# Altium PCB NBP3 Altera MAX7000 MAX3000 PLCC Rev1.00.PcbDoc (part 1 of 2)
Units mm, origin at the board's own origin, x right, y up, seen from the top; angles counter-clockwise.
Board outline 69 x 80.99 mm, 2 copper layers (Top Layer, Bottom Layer); 33 components, 75 nets, 412 pads, 171 vias.
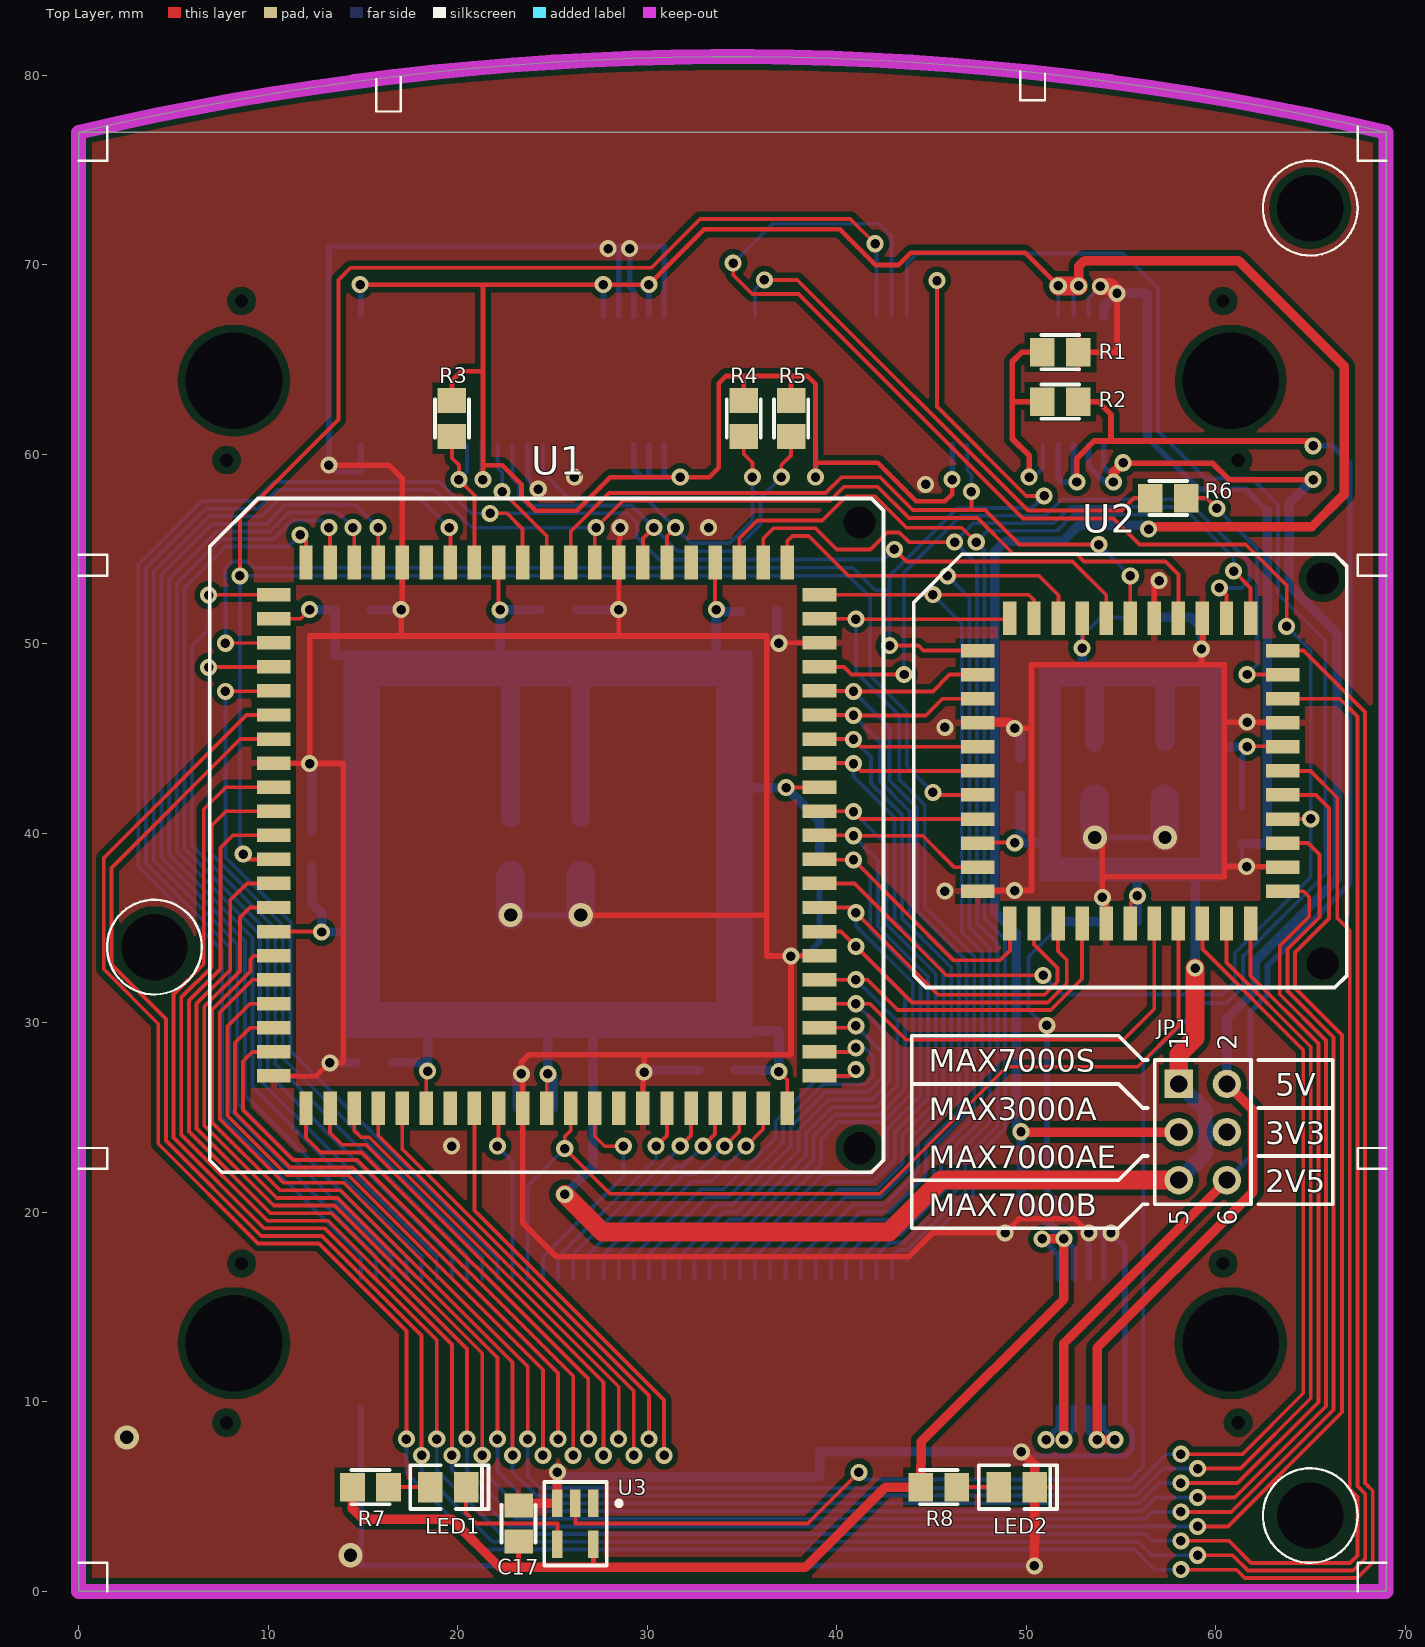
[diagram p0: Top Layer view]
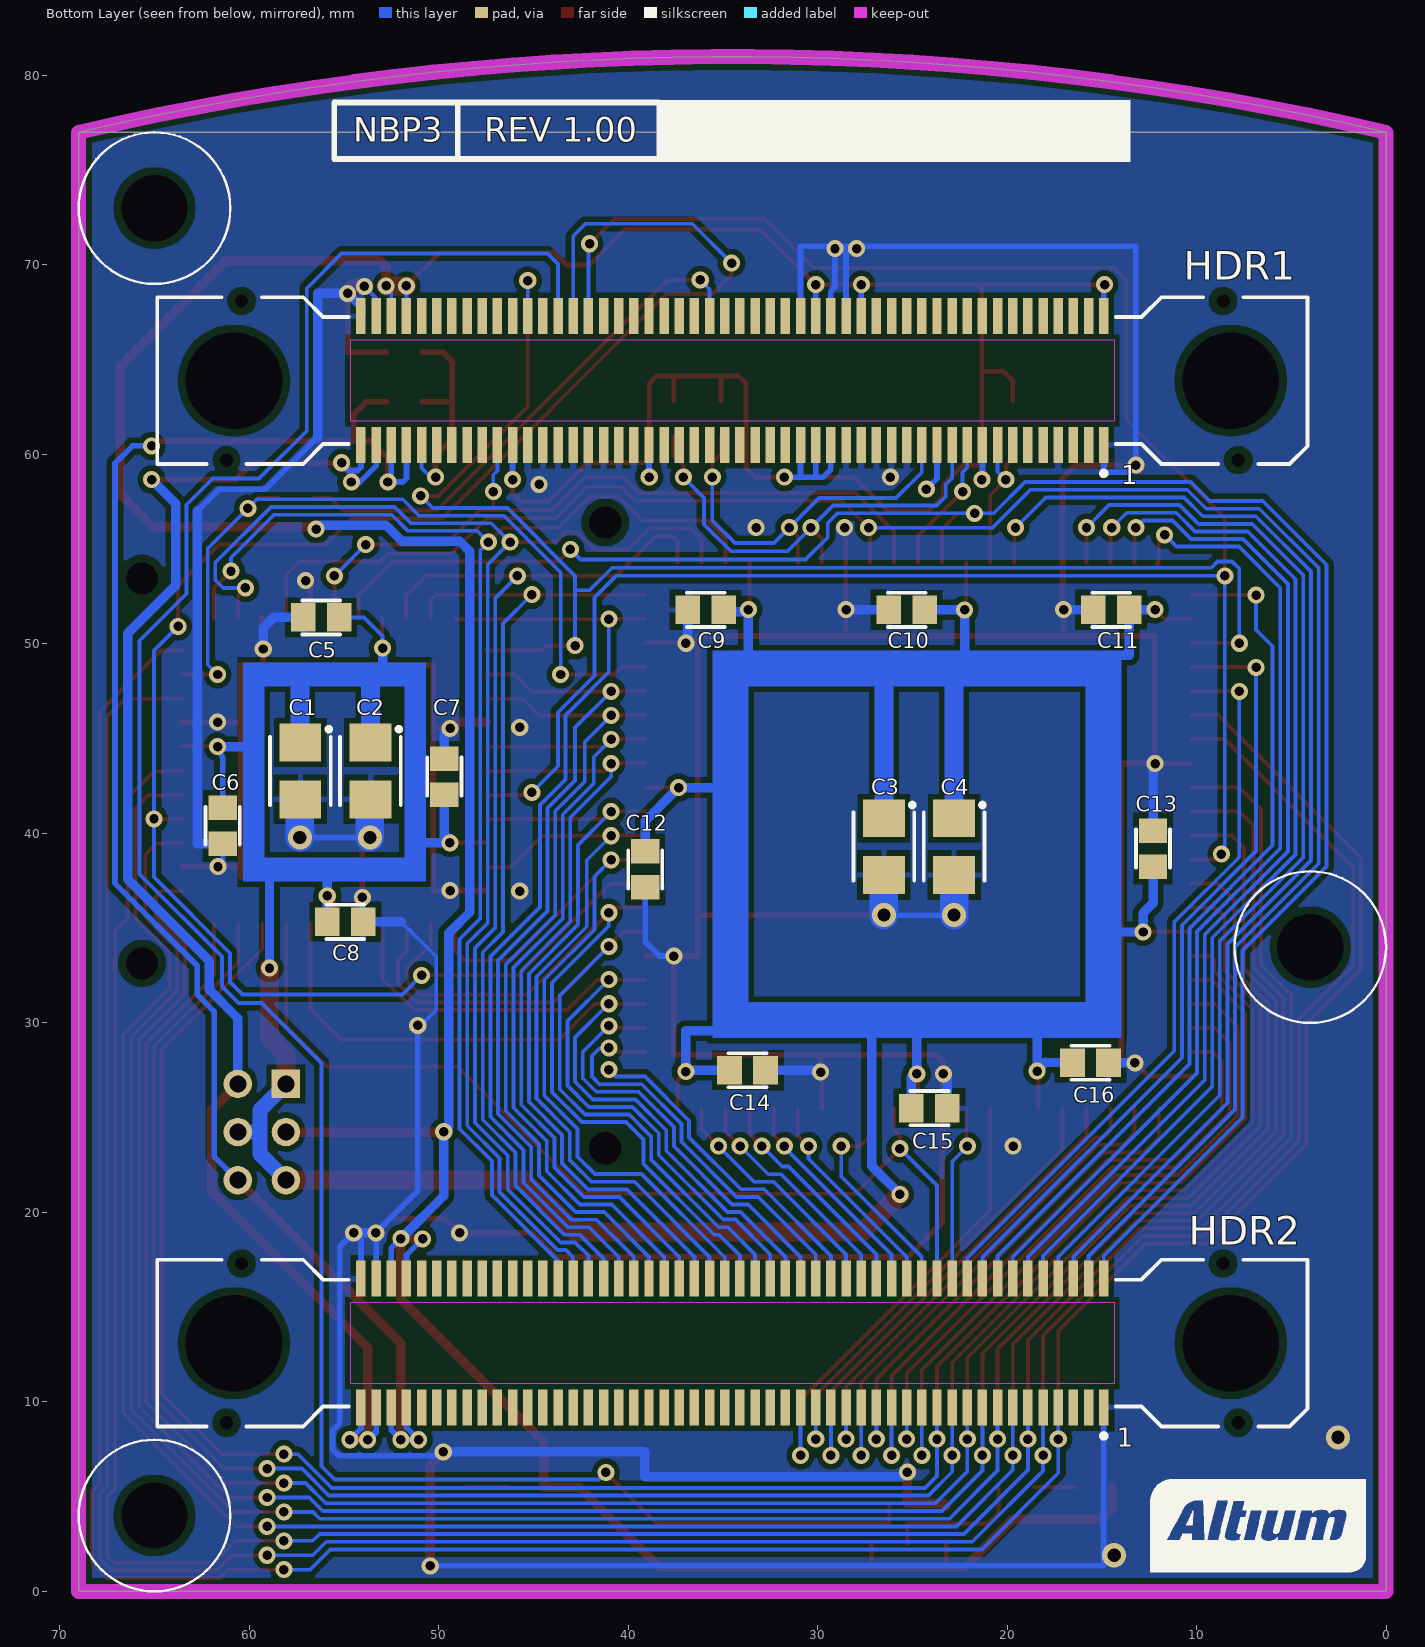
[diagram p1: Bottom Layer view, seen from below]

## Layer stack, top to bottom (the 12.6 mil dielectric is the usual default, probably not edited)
Top Layer: signal copper 0.0356
Dielectric: core 0.32, FR-4, Dk 4.8
Bottom Layer: signal copper 0.0356

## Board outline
0,0 0,77 ccw(c0.001,77) 0.001,77 cw(c34.5,-69.801) 0.001,77 69,77 69,0

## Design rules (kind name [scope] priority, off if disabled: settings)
Clearance Clearance_Unplated_Pads [PadIsPlated = 'False'] p1: gap=0.4 // Slightly larger clearance around unplated holes
Clearance Clearance_Polygons [InPolygon] p2: gap=0.3
Clearance [All] p3: gap=0.2
ComponentClearance [All] p1: gap=0.2 collisioncheckmode=3 verticalgap=0.254 showdistances=FALSE
FabricationTestPointUsage TestPointUsage [All] p1 off: valid=0 allowmultiple=FALSE
FabricationTestpoint Testpoint [All] p1 off: side=3 testpointundercomponent=TRUE minsize=1.016 maxsize=2.54 preferedsize=1.524 minholesize=0 maxholesize=1.016 preferedholesize=0.813 testpointgrid=0.025 allowsidetop=TRUE allowsidebottom=TRUE usegrid=TRUE gridtolerance=0
HoleSize [All] p1: absolutevalues=TRUE maxlimit=5.2 minlimit=0.4 maxpercent=80.000 minpercent=20.000
PlaneClearance [All] p1: clearance=0.5
PlaneConnect [All] p1: planeconnectstyle=Relief reliefexpansion=0.5 reliefentries=4 reliefconductorwidth=0.25 reliefairgap=0.25
PolygonConnect PolygonConnect_Satellite_ID_Pads [InPadClass('Satellite ID Pads')] p1: connectstyle=NoConnect reliefconductorwidth=0.254 reliefentries=4 polygonreliefangle="90 Angle"
PolygonConnect [All] p2: connectstyle=Relief reliefconductorwidth=0.3 reliefentries=4 polygonreliefangle="90 Angle"
RoutingVias [All] p1: holewidth=0.5 width=0.9 viastyle="Through Hole" minholewidth=0.5 minwidth=0.9 maxholewidth=0.7 maxwidth=1.27
SMDNeckDown [All] p1: percent=100.000
SilkscreenOverComponentPads [All] p1: minsilkscreentomaskgap=0.254
SolderMaskExpansion SolderMaskExpansion_Vias [Isvia] p1: expansion=-0.65
SolderMaskExpansion [All] p2: expansion=0.1
Width Width_Power_Nets [InNetClass('Power Nets')] p1: maxlimit=2.5 minlimit=0.15 preferedwidth=0.25
Width [All] p2: maxlimit=1.5 minlimit=0.2 preferedwidth=0.2
21 further rules are at their usual default settings.

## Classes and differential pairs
pad class "Satellite ID Pads": HDR1-36 HDR1-38 HDR2-42
net class "Power Nets": 5V GND VCC VCC_FPGA VCCINT

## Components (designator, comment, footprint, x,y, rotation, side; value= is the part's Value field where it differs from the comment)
C1 "10uF" MCCT-B 57.3,43.3 r270 bottom
C2 "10uF" MCCT-B 53.6,43.3 r270 bottom
C3 "10uF" MCCT-B 26.5,39.3 r270 bottom
C4 "10uF" MCCT-B 22.8,39.3 r270 bottom
C5 "0.1uF" CC2012-0805#1 56.2,51.4 r0 bottom
C6 "0.1uF" CC2012-0805#1 61.4,40.4 r270 bottom
C7 "0.1uF" CC2012-0805#1 49.7,43 r90 bottom
C8 "0.1uF" CC2012-0805#1 54.928,35.334 r180 bottom
C9 "0.1uF" CC2012-0805#1 35.9,51.8 r180 bottom
C10 "0.1uF" CC2012-0805#1 25.3,51.8 r180 bottom
C11 "0.1uF" CC2012-0805#1 14.5,51.8 r180 bottom
C12 "0.1uF" CC2012-0805#1 39.1,38.1 r270 bottom
C13 "0.1uF" CC2012-0805#1 12.3,39.2 r270 bottom
C14 "0.1uF" CC2012-0805#1 33.7,27.5 r180 bottom
C15 "0.1uF" CC2012-0805#1 24.1,25.5 r180 bottom
C16 "0.1uF" CC2012-0805#1 15.6,27.9 r180 bottom
C17 "0.1uF" CC2012-0805#2 23.217,3.571 r90 top
HDR1 "54075-1009" 54075 34.5,63.9 r0 bottom locked
HDR2 "54075-1009" 54075 34.5,13.1 r0 bottom locked
JP1 "Header 3X2" HDR2X3 58.06,26.78 r270 top
LED1 "HSMG-C170" "SMD _LED" 19.5,5.5 r180 top locked
LED2 "HSMH-C170" "SMD _LED" 49.5,5.5 r180 top locked
R1 "680R" CC2012-0805#1 51.8,65.4 r0 top
R2 "82R" CC2012-0805#1 51.8,62.787 r180 top
R3 "4K7" CC2012-0805#1 19.7,61.9 r270 top
R4 "4K7" CC2012-0805#1 35.1,61.9 r270 top
R5 "4K7" CC2012-0805#1 37.6,61.9 r270 top
R6 "100R" CC2012-0805#1 57.5,57.7 r0 top
R7 "270R" CC2012-0805#1 15.4,5.5 r0 top
R8 "270R" CC2012-0805#1 45.4,5.5 r0 top
U1 "PLCC84 SM Socket" PLCC84_SKT_SM 24.7,39.9 r0 top
U2 "PLCC44 SM Socket" PLCC44_SKT_SM 55.5,43.3 r0 top
U3 "SN74LVC1G04DBV" SO-G5/P.95 26.217,3.571 r180 top

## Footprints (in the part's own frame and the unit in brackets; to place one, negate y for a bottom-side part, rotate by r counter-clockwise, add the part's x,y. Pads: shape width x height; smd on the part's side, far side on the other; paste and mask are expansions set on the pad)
54075 [mm] "Connector; Docking Station, Receptacle; 100 Position; Vertical"
  rect 0.5x1.9 smd: 1(-19.6,3.4) 2(-19.6,-3.4) 3(-18.8,3.4) 4(-18.8,-3.4) 5(-18,3.4) 6(-18,-3.4) 7(-17.2,3.4) 8(-17.2,-3.4) 9(-16.4,3.4) 10(-16.4,-3.4) 11(-15.6,3.4) 12(-15.6,-3.4) 13(-14.8,3.4) 14(-14.8,-3.4) 15(-14,3.4) 16(-14,-3.4) 17(-13.2,3.4) 18(-13.2,-3.4) 19(-12.4,3.4) 20(-12.4,-3.4) 21(-11.6,3.4) 22(-11.6,-3.4) 23(-10.8,3.4) 24(-10.8,-3.4) 25(-10,3.4) 26(-10,-3.4) 27(-9.2,3.4) 28(-9.2,-3.4) 29(-8.4,3.4) 30(-8.4,-3.4) 31(-7.6,3.4) 32(-7.6,-3.4) 33(-6.8,3.4) 34(-6.8,-3.4) 35(-6,3.4) 36(-6,-3.4) 37(-5.2,3.4) 38(-5.2,-3.4) 39(-4.4,3.4) 40(-4.4,-3.4) 41(-3.6,3.4) 42(-3.6,-3.4) 43(-2.8,3.4) 44(-2.8,-3.4) 45(-2,3.4) 46(-2,-3.4) 47(-1.2,3.4) 48(-1.2,-3.4) 49(-0.4,3.4) 50(-0.4,-3.4) 51(0.4,3.4) 52(0.4,-3.4) 53(1.2,3.4) 54(1.2,-3.4) 55(2,3.4) 56(2,-3.4) 57(2.8,3.4) 58(2.8,-3.4) 59(3.6,3.4) 60(3.6,-3.4) 61(4.4,3.4) 62(4.4,-3.4) 63(5.2,3.4) 64(5.2,-3.4) 65(6,3.4) 66(6,-3.4) 67(6.8,3.4) 68(6.8,-3.4) 69(7.6,3.4) 70(7.6,-3.4) 71(8.4,3.4) 72(8.4,-3.4) 73(9.2,3.4) 74(9.2,-3.4) 75(10,3.4) 76(10,-3.4) 77(10.8,3.4) 78(10.8,-3.4) 79(11.6,3.4) 80(11.6,-3.4) 81(12.4,3.4) 82(12.4,-3.4) 83(13.2,3.4) 84(13.2,-3.4) 85(14,3.4) 86(14,-3.4) 87(14.8,3.4) 88(14.8,-3.4) 89(15.6,3.4) 90(15.6,-3.4) 91(16.4,3.4) 92(16.4,-3.4) 93(17.2,3.4) 94(17.2,-3.4) 95(18,3.4) 96(18,-3.4) 97(18.8,3.4) 98(18.8,-3.4) 99(19.6,3.4) 100(19.6,-3.4)
  round 0.5 hole 0.7 unplated: MH1(-26.7,4.2) MH2(-25.9,-4.2) MH3(26.7,4.2) MH4(25.9,-4.2)
  round 4.8 hole 5.1 unplated: MH5(-26.3,0) MH6(26.3,0)
  Top Layer keep-out region: -20.15,2.15 20.15,2.15 20.15,-2.15 -20.15,-2.15
  silkscreen extent -30.35,-4.4 30.35,5.02
CC2012-0805#1 [mm]
  rect 1.3x1.5 smd: 1(-0.95,0) 2(0.95,0)
  silkscreen extent -1,-0.9 1,0.9
CC2012-0805#2 [mm]
  rect 1.271x1.5 smd: 1(-0.95,0) 2(0.95,0)
  silkscreen extent -1,-0.9 1,0.9
HDR2X3 [mm] "Connector; Header; 3x2 Position"
  rect 1.5x1.5 hole 0.9: 1(0,0)
  round 1.5 hole 0.9: 2(0,2.54) 3(2.54,0) 4(2.54,2.54) 5(5.08,0) 6(5.08,2.54)
  silkscreen extent -1.27,-1.27 6.35,3.81
MCCT-B [mm]
  rect 2x2.2 smd: 1(-1.5,0) 2(1.5,0)
  silkscreen extent -2.3,-1.6 1.8,1.6
PLCC44_SKT_SM [mm] "Socket, PLCC44, surface mount"
  rect 0.71x1.78 smd: 1(0,8.05) 2(-1.27,8.05) 3(-2.54,8.05) 4(-3.81,8.05) 5(-5.08,8.05) 6(-6.35,8.05) 18(-6.35,-8.05) 19(-5.08,-8.05) 20(-3.81,-8.05) 21(-2.54,-8.05) 22(-1.27,-8.05) 23(0,-8.05) 24(1.27,-8.05) 25(2.54,-8.05) 26(3.81,-8.05) 27(5.08,-8.05) 28(6.35,-8.05) 40(6.35,8.05) 41(5.08,8.05) 42(3.81,8.05) 43(2.54,8.05) 44(1.27,8.05)
  rect 1.78x0.71 smd: 7(-8.05,6.35) 8(-8.05,5.08) 9(-8.05,3.81) 10(-8.05,2.54) 11(-8.05,1.27) 12(-8.05,0) 13(-8.05,-1.27) 14(-8.05,-2.54) 15(-8.05,-3.81) 16(-8.05,-5.08) 17(-8.05,-6.35) 29(8.05,-6.35) 30(8.05,-5.08) 31(8.05,-3.81) 32(8.05,-2.54) 33(8.05,-1.27) 34(8.05,0) 35(8.05,1.27) 36(8.05,2.54) 37(8.05,3.81) 38(8.05,5.08) 39(8.05,6.35)
  round 1.4 hole 1.7 unplated: M1(10.16,10.16) M2(10.16,-10.16)
  silkscreen extent -11.43,-11.43 11.43,11.43
PLCC84_SKT_SM [mm] "Socket, PLCC84, surface mount"
  rect 0.71x1.78 smd: 1(0,14.4) 2(-1.27,14.4) 3(-2.54,14.4) 4(-3.81,14.4) 5(-5.08,14.4) 6(-6.35,14.4) 7(-7.62,14.4) 8(-8.89,14.4) 9(-10.16,14.4) 10(-11.43,14.4) 11(-12.7,14.4) 33(-12.7,-14.4) 34(-11.43,-14.4) 35(-10.16,-14.4) 36(-8.89,-14.4) 37(-7.62,-14.4) 38(-6.35,-14.4) 39(-5.08,-14.4) 40(-3.81,-14.4) 41(-2.54,-14.4) 42(-1.27,-14.4) 43(0,-14.4) 44(1.27,-14.4) 45(2.54,-14.4) 46(3.81,-14.4) 47(5.08,-14.4) 48(6.35,-14.4) 49(7.62,-14.4) 50(8.89,-14.4) 51(10.16,-14.4) 52(11.43,-14.4) 53(12.7,-14.4) 75(12.7,14.4) 76(11.43,14.4) 77(10.16,14.4) 78(8.89,14.4) 79(7.62,14.4) 80(6.35,14.4) 81(5.08,14.4) 82(3.81,14.4) 83(2.54,14.4) 84(1.27,14.4)
  rect 1.78x0.71 smd: 12(-14.4,12.7) 13(-14.4,11.43) 14(-14.4,10.16) 15(-14.4,8.89) 16(-14.4,7.62) 17(-14.4,6.35) 18(-14.4,5.08) 19(-14.4,3.81) 20(-14.4,2.54) 21(-14.4,1.27) 22(-14.4,0) 23(-14.4,-1.27) 24(-14.4,-2.54) 25(-14.4,-3.81) 26(-14.4,-5.08) 27(-14.4,-6.35) 28(-14.4,-7.62) 29(-14.4,-8.89) 30(-14.4,-10.16) 31(-14.4,-11.43) 32(-14.4,-12.7) 54(14.4,-12.7) 55(14.4,-11.43) 56(14.4,-10.16) 57(14.4,-8.89) 58(14.4,-7.62) 59(14.4,-6.35) 60(14.4,-5.08) 61(14.4,-3.81) 62(14.4,-2.54) 63(14.4,-1.27) 64(14.4,0) 65(14.4,1.27) 66(14.4,2.54) 67(14.4,3.81) 68(14.4,5.08) 69(14.4,6.35) 70(14.4,7.62) 71(14.4,8.89) 72(14.4,10.16) 73(14.4,11.43) 74(14.4,12.7)
  round 1.4 hole 1.7 unplated: M1(16.51,16.51) M2(16.51,-16.51)
  silkscreen extent -17.78,-17.78 17.78,17.78
"SMD _LED" [mm]
  rect 1.3x1.6 smd: 1(0.95,0) 2(-0.95,0)
  silkscreen extent -2.13,-1.15 2,1.15
SO-G5/P.95 [mm]
  rect 0.55x1.45 smd: 1(-0.95,-1.075) 2(0,-1.075) 3(0.95,-1.075) 4(0.95,1.075) 5(-0.95,1.075)
  silkscreen extent -2.43,-2.2 1.65,2.2

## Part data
C1 C2 C3 C4: library part CAP_POLAR, "Polar Capacitor"
C5 C6 C7 C8 C9 C10 C11 C12 C13 C14 C15 C16 C17: library part CAP, "Capacitor"
HDR1 HDR2: "Board-to-Board, Docking Station, 0.80mm (.031\") Pitch, Shielded Receptacle, Vertical, Ultra Low Profile, SMT"
JP1: "Header, 3-Pin, Dual row"
LED1 LED2: library part HSMX-C670, "Typical RED GaAs SMD LED Agilent make"
R1 R2 R3 R4 R5 R6 R7 R8: library part RES, "Resistor"
U1: library part EPM7160SLC84-10, "MAX 7000S 5V In-System Programmable CPLD, 160 Macrocells, 84-Pin PLCC, Speed Grade 10, Commercial Grade"
U2: library part EPM3032ALC44-10, "MAX 3032, 44-Pin PLCC, Speed Grade 10, Commercial Grade"
U3: library part SN74AHC1G04DBVR

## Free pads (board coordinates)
  round 3.2 hole 3.5 unplated: LP(4,34) LP(65,4) LP(65,73)

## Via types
v1: diameter 0.9, hole 0.5, Top Layer to Bottom Layer, 165 vias
v2: diameter 1.27, hole 0.7, Top Layer to Bottom Layer, 6 vias

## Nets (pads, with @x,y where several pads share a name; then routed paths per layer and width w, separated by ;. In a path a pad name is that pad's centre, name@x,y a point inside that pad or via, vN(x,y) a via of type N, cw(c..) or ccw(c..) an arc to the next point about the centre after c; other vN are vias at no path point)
5V: HDR1.97 HDR1.99 HDR2.97 HDR2.99 JP1.2 | length 84.1
  Top Layer w0.3: v1(55.118,59.563) 55.601,59.538 59.842,59.538 60.706,58.674 v1(65.151,58.674)
  Top Layer w0.5: v1(54.61,58.547) 54.61,59.055 v1(55.118,59.563) ; v1(54.686,8.001) v1(53.746,8.001) 53.746,12.852 61.976,21.082 61.976,25.404 JP1.2@60.6,26.78
  Bottom Layer w0.3: HDR1.97@53.3,60.5 53.3,59.4 54.178,58.522 v1(54.61,58.547) ; HDR1.99@54.1,60.5 54.1,59.336 54.28,59.157 54.762,59.157 v1(55.118,59.563) ; 54.1,8.587 HDR2.99@54.1,9.7 54.1,8.587 ; 54.1,8.587 v1(54.686,8.001) 54.1,8.587 ; 53.3,8.371 v1(53.746,8.001) 53.3,8.447 HDR2.97@53.3,9.7 53.3,8.371
  Bottom Layer w0.5: JP1.2@60.6,26.78 60.6,30.247 62.103,31.75 62.103,33.274 66.421,37.592 66.421,50.546 63.881,53.086 63.881,57.404 v1(65.151,58.674)
BOC_RX: HDR1.19 U1.1 | length 7.3
  Top Layer w0.2: v1(22.352,58.039) 24.7,55.691 U1.1@24.7,54.3
  Bottom Layer w0.2: HDR1.19@22.1,60.5 22.1,59.307 22.352,59.055 v1(22.352,58.039)
BOC_TX: HDR1.15 R3.2 U1.4 | length 9.1
  Top Layer w0.2: R3.2@19.7,60.95 19.7,59.802 20.066,59.436 v1(20.066,58.674) 20.89,57.85 U1.4@20.89,54.3
  Bottom Layer w0.2: v1(20.066,58.674) 20.5,59.108 HDR1.15@20.5,60.5
BUZZER: HDR2.24 U1.44 U2.25 | length 52.4
  Top Layer w0.2: U1.44@25.97,25.5 25.97,24.319 25.654,24.003 v1(25.654,23.368) 28.034,20.988 42.282,20.988 48.98,27.686 55.895,27.686 58.04,29.831 U2.25@58.04,35.25
  Bottom Layer w0.2: HDR2.24@23.7,16.5 23.7,21.414 v1(25.654,23.368)
FPGA_CLK: HDR2.2 U1.2 U2.2 | length 103.8
  Top Layer w0.2: v1(21.717,56.896) 22.606,56.896 23.43,56.072 U1.2@23.43,54.3 ; v1(43.053,54.991) 43.688,54.356 52.451,54.356 54.23,52.577 U2.2@54.23,51.35
  Bottom Layer w0.2: HDR2.2@14.9,16.5 14.9,17.7 7.575,25.025 7.575,33.827 3.15,38.252 3.15,54.178 6.508,57.537 9.302,57.537 10.312,58.547 19.05,58.547 20.701,56.896 28.956,56.896 29.464,56.388 29.464,55.626 30.632,54.458 42.52,54.458 v1(43.053,54.991)
FPGA_DONE: HDR1.74 U3.2 | length 121.5
  Top Layer w0.2: U3.2@26.217,4.646 26.217,3.581 38.481,3.581 v1(41.173,6.274)
  Bottom Layer w0.2: v1(41.173,6.274) 41.542,5.905 55.486,5.905 56.185,6.604 56.185,27.889 59.345,31.05 60.572,31.05 61.443,31.921 61.443,33.503 65.786,37.846 65.786,50.165 63.304,52.647 63.304,57.346 61.923,58.727 59.476,58.727 56.963,61.239 56.963,68.767 55.126,70.604 44.255,70.604 43.7,70.049 HDR1.74@43.7,67.3
FPGA_TCK: HDR1.72 U1.62 U2.32 | length 99.5
  Top Layer w0.2: v1(34.544,70.104) 34.544,69.469 35.55,68.463 37.986,68.463 49.832,56.617 54.61,56.617 55.982,55.245 61.595,55.245 63.754,53.086 v1(63.754,50.927) ; U1.62@39.1,37.36 40.945,37.36 45.793,32.512 v1(50.902,32.512) ; U2.32@63.55,40.763 v1(65.024,40.767)
  Bottom Layer w0.2: v1(34.544,70.104) 36.614,72.174 42.253,72.174 42.9,71.527 HDR1.72@42.9,67.3 ; v1(50.902,32.512) 51.91,31.504 60.358,31.504 61.011,32.156 61.011,33.68 65.024,37.694 65.024,49.657 v1(63.754,50.927)
FPGA_TDI: HDR1.78 U1.14 U2.7 | length 76.8
  Top Layer w0.2: v1(7.747,50.038) U1.14@10.3,50.06 ; v1(42.799,49.911) 44.316,49.911 44.577,49.65 U2.7@47.45,49.65 ; v1(45.3,69.176) 45.3,62.523 50.013,57.81 v1(50.952,57.81) ; U2.7@47.45,49.684 U2.7@47.478,49.684
  Bottom Layer w0.2: v1(7.747,50.038) 7.747,53.975 8.128,54.356 8.89,54.356 9.22,54.026 40.843,54.026 42.037,52.832 42.799,52.832 ; v1(42.799,49.911) 42.799,53.594 46.374,57.169 50.311,57.169 v1(50.952,57.81) ; HDR1.78@45.3,67.3 v1(45.3,69.176)
FPGA_TDO: HDR1.54 R6.1 | length 27.8
  Top Layer w0.2: v1(36.195,69.215) 37.926,69.215 50.104,57.038 55.042,57.038 55.704,57.7 R6.1@56.55,57.7
  Bottom Layer w0.2: HDR1.54@35.7,67.3 35.7,68.72 v1(36.195,69.215)
FPGA_TDO#: R6.2 U1.71 U2.38 | length 41.9
  Top Layer w0.2: U1.71@39.1,48.79 40.386,48.79 40.789,48.387 v1(43.561,48.387) ; R6.2@58.45,57.7 59.521,57.7 v1(60.071,57.15) ; v1(61.671,48.387) 61.983,48.38 U2.38@63.55,48.38 ; U2.38@63.549,48.414 U2.38@63.578,48.414
  Bottom Layer w0.2: v1(43.561,48.387) 43.561,53.772 46.558,56.769 51.035,56.769 51.899,57.633 59.588,57.633 62.188,55.033 62.188,48.904 v1(61.671,48.387)
FPGA_TMS: HDR1.70 U1.23 U2.13 | length 116.1
  Top Layer w0.2: v1(8.509,53.594) 8.509,56.642 13.716,61.849 13.716,69.215 14.351,69.85 30.226,69.85 32.809,72.433 40.724,72.433 v1(42.037,71.12) ; v1(8.687,38.913) 8.97,38.63 U1.23@10.3,38.63 ; v1(45.085,42.164) 45.473,42.03 U2.13@47.45,42.03
  Bottom Layer w0.2: v1(8.687,38.913) 8.509,39.091 v1(8.509,53.594) 40.64,53.594 41.783,52.451 41.783,48.318 43.707,46.394 43.707,43.542 v1(45.085,42.164) v1@45.085,42.167 ; v1(42.037,71.12) 42.1,71.057 HDR1.70@42.1,67.3
GND: C1.2 C2.2 C3.2 C4.2 C5.2 C6.2 C7.2 C8.2 C9.1 C10.1 C11.1 C12.2 C13.1 C14.2 C15.2 C16.2 C17.2 HDR1.1 HDR1.7 HDR1.23 HDR1.27 HDR1.29 HDR1.31 HDR1.33 HDR1.35 HDR1.36 HDR1.38 HDR1.42 HDR1.59 HDR1.63 HDR1.65 HDR1.67 HDR1.69 HDR1.71 HDR1.73 HDR1.75 HDR1.77 HDR1.98 HDR1.100 HDR2.1 HDR2.98 HDR2.100 LED2.2 R1.2 U1.7 U1.19 U1.32 U1.42 U1.47 U1.59 U1.72 U1.82 U2.10 U2.17 U2.22 U2.30 U2.36 U2.42 U2.44 U3.3 | length 489.5
  Top Layer w0.25: U1.32@10.3,27.2 10.322,27.178 12.55,27.203 v1(13.259,27.889) ; U1.19@10.3,43.71 10.322,43.688 v1(12.192,43.688) ; U1.42@23.43,25.5 23.43,26.649 ; 28.51,50.419 28.51,55.434 28.575,55.499 v1(28.575,56.134) ; U1.47@29.78,25.5 v1@29.78,27.335 ; 36.322,50.038 v1(36.957,50.038) ; v1@36.979,50.06 U1.72@39.1,50.06 ; v1(37.592,33.528) 39.078,33.528 U1.59@39.1,33.55 ; v1(54.026,36.627) 54.258,36.395 U2.22@54.258,35.284 ; v1(61.646,38.252) 63.55,38.254 U2.30@63.578,38.254
  Top Layer w0.3: v1(13.208,59.436) 16.383,59.436 17.08,58.739 U1.7@17.08,54.3 17.08,51.878 v1(17.018,51.816) 17.018,50.419 ; v1(13.259,27.889) 13.97,27.889 13.97,43.688 v1(12.192,43.688) 12.192,50.419 17.018,50.419 ; v2(26.5,35.689) 36.322,35.689 ; v1(29.845,27.4) 29.845,28.321 ; U2.17@47.478,36.984 50.292,36.984 50.292,48.895 60.452,48.895 60.452,37.719 54.026,37.719 ; v1(49.4,45.545) 50.292,45.545 ; R1.2@52.75,65.4 54.8,65.4 v1(54.8,68.5) ; v1(53.315,18.923) 52.578,19.66 49.632,19.66 v1(48.895,18.923) 45.072,18.923 43.802,17.653 25.233,17.653 23.43,19.456 U1.42@23.43,25.5 23.43,27.243 v1(23.368,27.305) 23.368,27.94 23.749,28.321 29.845,28.321 ; v2(53.628,39.785) 54.026,39.785 v1(54.026,36.627) ; U2.44@56.77,51.35 56.77,53.087 v1(57.023,53.34) ; 59.259,48.895 v1(59.259,49.734) 59.338,49.813 U2.42@59.338,51.384 ; 60.452,38.252 v1(61.646,38.252) ; 60.452,45.872 v1(61.671,45.872) 63.55,45.874 U2.36@63.578,45.874 ; 17.018,50.419 36.322,50.419 36.322,50.038 36.322,33.528 v1(37.592,33.528) 37.592,28.321 29.845,28.321
  Top Layer w0.5: C17.2@23.217,4.521 23.342,4.646 U3.3@25.267,4.646 v1(25.267,6.294) ; U2.10@47.478,45.874 49.071,45.874 v1(49.4,45.545) ; v1(49.759,7.366) 50.45,6.675 50.45,3.652 v1(50.444,1.346)
  Top Layer w0.9: v1(53.925,68.875) 54.425,68.875 v1(54.8,68.5)
  Bottom Layer w0.2: v1(51.105,29.87) 50.942,29.87 50.129,30.683 50.129,33.492 51.971,35.334 ; HDR1.98@53.3,67.3 53.3,68.25 v1(53.925,68.875) ; C6.2@61.4,39.45 61.4,38.498 v1(61.646,38.252)
  Bottom Layer w0.25: C8.2@53.978,35.334 v1(54.026,36.627)
  Bottom Layer w0.3: HDR2.1@14.9,9.7 14.91,1.346 v1(50.444,1.346) ; HDR1.1@14.9,60.5 14.9,59.055 13.589,59.055 v1(13.208,59.436) 13.208,70.993 30.9,70.993 HDR1.42@30.9,67.3 ; v2(22.8,35.689) v2(26.5,35.689) ; HDR1.23@23.7,60.5 23.7,58.723 v1(24.257,58.166) ; HDR1.36@28.5,67.3 28.5,70.993 ; v1@29.083,70.993 29.083,68.834 29.3,68.617 HDR1.38@29.3,67.3 ; v1(37.592,33.528) 38.354,33.528 39.1,34.274 C12.2@39.1,37.15 ; v1(49.759,7.366) 49.962,7.163 55.27,7.163 55.6,7.492 55.6,8.484 55.22,8.865 55.22,18.186 v1(54.483,18.923) 54.1,18.54 HDR2.100@54.1,16.5 ; v1(51.105,29.87) 51.105,21.133 v1(53.315,18.923) 53.3,18.908 HDR2.98@53.3,16.5 ; v2(53.628,39.785) v2(57.328,39.785) ; 56.388,60.909 59.131,58.166 61.595,58.166 62.738,57.023
  Bottom Layer w0.5: v1(12.192,43.688) 12.3,43.58 C13.1@12.3,40.15 ; v1(13.259,27.889) C16.2@14.65,27.9 ; C11.1@15.45,51.8 v1@17.002,51.8 ; C15.2@23.15,25.5 v1@23.15,27.015 ; v1(25.267,6.294) 25.506,6.055 39.116,6.055 39.116,7.366 v1(49.759,7.366) ; C10.1@26.25,51.8 v1@28.5,51.8 ; v1(29.845,27.4) 29.945,27.5 C14.2@32.75,27.5 ; C9.1@36.85,51.8 36.85,50.145 v1(36.957,50.038) ; v1(49.4,45.545) 49.7,45.245 C7.2@49.7,43.95 ; 51.971,35.334 C8.2@53.978,35.334 ; v1(53.315,18.923) v1(54.483,18.923) ; HDR1.100@54.1,67.3 54.1,67.825 v1(54.8,68.5) 56.388,68.5 56.388,60.909 ; C5.2@57.15,51.4 58.709,51.4 59.259,50.85 v1(59.259,49.734) ; C6.2@61.4,39.45 62.738,39.45 62.738,57.023
  Bottom Layer w1.5: v2(22.8,35.689) C4.2@22.8,37.8 ; v2(26.5,35.689) C3.2@26.5,37.8 ; v2(53.628,39.785) C2.2@53.628,41.834 ; v2(57.328,39.785) C1.2@57.328,41.834
  other v1: 19.685,23.495 45.72,36.957 49.396,36.984 45.72,45.593 28.499,51.816 33.25,56.134 44.704,58.42 26.162,58.8 27.94,70.866 29.083,70.866
  other v2: 14.351,1.905 2.54,8.128
IO0: HDR2.7 U1.17 U2.39 | length 159.1
  Top Layer w0.2: U1.17@10.3,46.25 8.865,46.25 1.321,38.706 1.321,32.842 4.204,29.959 4.204,23.622 9.468,18.358 12.677,18.358 17.3,13.735 v1(17.3,8.029) ; v1(58.166,1.143) 61.099,1.143 61.542,0.7 67.477,0.7 68.3,1.523 68.3,5.31 67.894,5.716 67.894,46.406 64.65,49.65 U2.39@63.55,49.65
  Bottom Layer w0.2: HDR2.7@17.3,9.7 17.3,6.246 21.33,2.216 55.721,2.216 56.794,1.143 v1(58.166,1.143)
IO1: HDR2.9 U1.18 U2.37 | length 155.6
  Top Layer w0.2: U1.18@10.3,44.98 8.531,44.98 1.727,38.176 1.727,33.09 4.604,30.213 4.604,23.788 9.633,18.758 12.842,18.758 18.1,13.5 v1(18.1,7.173) ; v1(59.055,1.905) 60.902,1.905 61.707,1.1 67.267,1.1 67.9,1.733 67.9,5.144 67.488,5.556 67.488,46.177 66.555,47.11 U2.37@63.55,47.11
  Bottom Layer w0.2: HDR2.9@18.1,9.7 18.1,6.36 21.844,2.616 55.931,2.616 56.642,1.905 v1(59.055,1.905)
IO2: HDR2.11 U1.20 U2.34 | length 143.7
  Top Layer w0.2: U1.20@10.3,42.44 7.769,42.44 6.604,41.275 6.604,33.095 5.004,31.495 5.004,23.953 9.799,19.158 13.008,19.158 18.9,13.266 v1(18.9,8.029) ; v1(58.166,2.667) 60.706,2.667 61.873,1.5 67.101,1.5 67.5,1.899 67.5,4.978 67.081,5.397 67.081,34.874 66.421,35.535 66.421,41.885 65.006,43.3 U2.34@63.55,43.3
  Bottom Layer w0.2: HDR2.11@18.9,9.7 18.9,6.412 22.283,3.029 56.28,3.029 56.642,2.667 v1(58.166,2.667)
IO3: HDR2.13 U1.21 U2.33 | length 135.7
  Top Layer w0.2: U1.21@10.3,41.17 7.769,41.17 7.004,40.405 7.004,32.93 5.41,31.336 5.41,24.113 9.965,19.558 13.174,19.558 19.7,13.032 v1(19.7,7.173) ; v1(59.055,3.429) 60.655,3.429 66.675,9.449 66.675,29.359 64.192,31.842 64.192,33.712 65.996,35.516 65.996,41.345 65.31,42.03 U2.33@63.55,42.03
  Bottom Layer w0.2: HDR2.13@19.7,9.7 19.7,6.401 22.672,3.429 v1(59.055,3.429)
IO4: HDR2.15 U1.22 U2.31 | length 128.6
  Top Layer w0.2: U1.22@10.3,39.9 8.15,39.9 7.493,39.243 7.493,32.853 5.817,31.177 5.817,24.272 10.131,19.958 13.339,19.958 20.5,12.797 v1(20.5,8.029) ; v1(58.166,4.191) 60.833,4.191 66.229,9.587 66.229,29.24 63.792,31.676 63.792,33.889 65.481,35.578 65.481,38.888 64.879,39.49 U2.31@63.55,39.49
  Bottom Layer w0.2: HDR2.15@20.5,9.7 20.5,6.375 23.04,3.835 56.277,3.835 56.632,4.191 v1(58.166,4.191)
IO5: HDR2.17 U1.24 U2.29 | length 121.9
  Top Layer w0.2: U1.24@10.3,37.36 8.88,37.36 8.001,36.481 8.001,32.795 6.223,31.017 6.223,24.431 10.296,20.358 13.505,20.358 21.3,12.563 v1(21.3,7.173) ; v1(59.055,4.953) 61.011,4.953 65.829,9.771 65.829,29.074 63.392,31.511 63.392,34.055 64.948,35.611 64.948,36.652 64.65,36.95 U2.29@63.55,36.95
  Bottom Layer w0.2: HDR2.17@21.3,9.7 21.3,6.375 23.434,4.242 56.118,4.242 56.829,4.953 v1(59.055,4.953)
IO6: HDR2.19 U1.25 U2.28 | length 115
  Top Layer w0.2: U1.25@10.3,36.09 9.039,36.09 8.509,35.56 8.509,32.738 6.629,30.858 6.629,24.591 10.453,20.767 13.662,20.767 22.1,12.329 v1(22.1,8.029) ; v1(58.166,5.715) 61.163,5.715 65.429,9.981 65.429,28.908 61.85,32.487 U2.28@61.85,35.25
  Bottom Layer w0.2: HDR2.19@22.1,9.7 22.1,6.325 23.776,4.648 55.958,4.648 57.025,5.715 v1(58.166,5.715)
IO7: HDR2.21 U1.27 U2.27 | length 111.9
  Top Layer w0.2: U1.27@10.3,33.55 9.268,33.55 9.068,33.35 9.068,32.731 7.036,30.699 7.036,24.75 10.619,21.167 13.827,21.167 22.9,12.094 v1(22.9,7.173) ; v1(59.055,6.477) 61.316,6.477 65.029,10.19 65.029,28.743 60.58,33.191 U2.27@60.58,35.25
  Bottom Layer w0.2: HDR2.21@22.9,9.7 22.9,6.31 24.155,5.055 55.799,5.055 57.221,6.477 v1(59.055,6.477)
IO8: HDR2.23 U1.28 U2.26 | length 108.5
  Top Layer w0.2: U1.28@10.3,32.28 9.183,32.28 7.442,30.54 7.442,24.943 10.818,21.567 13.993,21.567 23.7,11.86 v1(23.7,8.029) ; v1(58.166,7.239) 61.417,7.239 64.629,10.451 64.629,28.577 59.31,33.896 U2.26@59.31,35.25
  Bottom Layer w0.2: HDR2.23@23.7,9.7 23.7,6.096 24.335,5.461 55.64,5.461 57.418,7.239 v1(58.166,7.239)
IO9: HDR2.25 U1.29 | length 36.9
  Top Layer w0.2: U1.29@10.3,31.01 9.039,31.01 7.849,29.82 7.849,25.102 10.984,21.967 14.228,21.967 24.5,11.695 v1(24.5,7.173)
  Bottom Layer w0.2: v1(24.5,7.173) HDR2.25@24.5,9.7
IO10: HDR2.27 U1.30 | length 34
  Top Layer w0.2: U1.30@10.3,29.74 9.039,29.74 8.255,28.956 8.255,25.261 11.149,22.367 14.463,22.367 25.3,11.53 v1(25.3,8.029)
  Bottom Layer w0.2: v1(25.3,8.029) HDR2.27@25.3,9.7
IO11: HDR2.29 U1.31 | length 34.4
  Top Layer w0.2: U1.31@10.3,28.47 9.166,28.47 8.673,27.977 8.673,25.409 11.315,22.767 14.698,22.767 26.1,11.365 v1(26.1,7.173)
  Bottom Layer w0.2: v1(26.1,7.173) HDR2.29@26.1,9.7
IO12: HDR2.31 U1.33 | length 26.6
  Top Layer w0.2: U1.33@12,25.5 12,23.941 12.774,23.167 14.933,23.167 26.9,11.2 v1(26.9,8.029)
  Bottom Layer w0.2: v1(26.9,8.029) HDR2.31@26.9,9.7
IO13: HDR2.33 U1.34 | length 27.6
  Top Layer w0.2: U1.34@13.27,25.5 13.27,24.195 13.898,23.567 15.168,23.567 27.7,11.035 v1(27.7,7.173)
  Bottom Layer w0.2: v1(27.7,7.173) HDR2.33@27.7,9.7
IO14: HDR2.35 U1.35 | length 25.2
  Top Layer w0.2: U1.35@14.54,25.5 14.54,24.322 14.895,23.967 15.334,23.967 28.5,10.801 v1(28.5,8.029)
  Bottom Layer w0.2: v1(28.5,8.029) HDR2.35@28.5,9.7
IO15: HDR2.37 U1.36 | length 26.4
  Top Layer w0.2: U1.36@15.81,25.5 15.81,24.056 29.3,10.566 v1(29.3,7.173)
  Bottom Layer w0.2: v1(29.3,7.173) HDR2.37@29.3,9.7
IO16: HDR2.39 U1.37 | length 24.5
  Top Layer w0.2: U1.37@17.08,25.5 17.08,23.352 30.1,10.332 v1(30.1,8.029)
  Bottom Layer w0.2: v1(30.1,8.029) HDR2.39@30.1,9.7
IO17: HDR2.41 U1.40 | length 25
  Top Layer w0.2: U1.40@20.89,25.5 20.89,20.108 30.9,10.098 v1(30.9,7.173)
  Bottom Layer w0.2: v1(30.9,7.173) HDR2.41@30.9,9.7
LCD_BCKL: HDR2.22 U1.41 | length 9.4
  Top Layer w0.2: v1(22.098,23.495) 22.16,23.557 U1.41@22.16,25.5
  Bottom Layer w0.2: v1(22.098,23.495) 22.9,22.693 HDR2.22@22.9,16.5
LCD_E: HDR2.26 U1.45 | length 12
  Top Layer w0.2: U1.45@27.24,25.5 27.24,24.017 27.762,23.495 v1(28.753,23.495)
  Bottom Layer w0.2: HDR2.26@24.5,16.5 24.5,17.642 28.753,21.895 v1(28.753,23.495)
LED0: HDR2.60 U1.68 U2.11 | length 43.4
  Top Layer w0.2: U1.68@39.1,44.98 40.872,44.98 41.282,44.57 U2.11@47.45,44.57
  Bottom Layer w0.2: HDR2.60@38.1,16.5 38.1,17.653 40.862,20.415 42.539,20.415 44.298,22.174 44.298,23.772 46.05,25.525 46.05,32.916 43.453,35.513 43.453,41.007 41.816,42.643 41.816,44.036 v1(40.894,44.958)
LED1: HDR2.62 U1.69 U2.9 | length 44.8
  Top Layer w0.2: U1.69@39.1,46.25 40.872,46.25 v1(40.894,46.228) 44.704,46.228 45.586,47.11 U2.9@47.45,47.11
  Bottom Layer w0.2: HDR2.62@38.9,16.5 38.9,17.653 41.262,20.015 42.774,20.015 44.704,21.946 44.704,23.613 46.457,25.366 46.457,33.075 43.853,35.679 43.853,41.172 42.291,42.734 42.291,44.831 v1(40.894,46.228)
LED2: HDR2.64 U1.70 U2.8 | length 45.9
  Top Layer w0.2: U1.70@39.1,47.52 v1@40.872,47.52 ; v1(40.894,47.498) 45.085,47.498 45.967,48.38 U2.8@47.45,48.38
  Bottom Layer w0.2: HDR2.64@39.7,16.5 39.7,17.653 41.662,19.615 42.983,19.615 45.11,21.742 45.11,23.454 46.863,25.206 46.863,33.299 44.253,35.909 44.253,41.338 42.799,42.792 42.799,45.593 v1(40.894,47.498)
LED3: HDR2.66 U1.73 U2.6 | length 51
  Top Layer w0.2: U1.73@39.1,51.33 40.999,51.33 v1(41.021,51.308) ; v1@41.063,51.35 v1(41.021,51.308) ; U2.6@49.15,51.35 49.108,51.308 v1(41.021,51.308)
  Bottom Layer w0.2: HDR2.66@40.5,16.5 40.5,17.653 42.062,19.215 43.168,19.215 45.517,21.565 45.517,23.294 47.269,25.047 47.269,33.503 44.653,36.119 44.653,41.504 43.307,42.85 43.307,46.228 41.021,48.514 v1(41.021,51.308)
LED4: HDR2.68 U1.74 U2.5 | length 52.7
  Top Layer w0.2: U1.74@39.1,52.6 50.143,52.6 50.42,52.323 U2.5@50.42,51.35
  Bottom Layer w0.2: HDR2.68@41.3,16.5 41.3,17.57 42.545,18.815 43.352,18.815 45.949,21.412 45.949,23.161 47.676,24.888 47.676,33.731 46.609,34.798 46.609,51.076 v1(45.085,52.6)
LED5: HDR2.70 U1.75 U2.4 | length 59
  Top Layer w0.2: U1.75@37.4,54.3 37.4,55.434 37.668,55.702 38.532,55.702 40.64,53.594 50.692,53.594 51.718,52.568 51.718,51.378 U2.4@51.69,51.35
  Bottom Layer w0.2: HDR2.70@42.1,16.5 42.1,17.716 42.799,18.415 43.555,18.415 46.355,21.216 46.355,23.001 48.082,24.728 48.082,33.96 47.009,35.033 47.009,52.432 v1(45.847,53.594)
LED6: HDR2.72 U1.76 U2.41 | length 77
  Top Layer w0.2: U1.76@36.13,54.3 36.13,55.561 36.678,56.109 38.887,56.109 40.005,54.991 41.783,54.991 42.672,55.88 43.307,55.88 43.815,55.372 v1(46.228,55.372) ; v1(60.198,52.959) 60.58,52.577 U2.41@60.58,51.35
  Bottom Layer w0.2: HDR2.72@42.926,16.5 42.926,17.653 43.288,18.015 43.72,18.015 46.787,21.082 46.787,22.867 48.489,24.569 48.489,34.188 47.409,35.268 47.409,54.191 v1(46.228,55.372) 47.225,56.369 51.46,56.369 52.317,57.226 58.852,57.226 61.788,54.29 61.788,53.381 61.366,52.959 v1(60.198,52.959)
LED7: HDR2.74 U1.77 U2.40 | length 75.1
  Top Layer w0.2: U1.77@34.86,54.3 34.86,55.561 35.814,56.515 39.243,56.515 40.513,57.785 42.037,57.785 43.688,56.134 46.609,56.134 v1(47.371,55.372) ; v1(60.96,53.848) 61.85,52.958 U2.40@61.85,51.35
  Bottom Layer w0.2: HDR2.74@43.7,17.43 47.193,20.923 47.193,22.708 48.895,24.41 48.895,34.417 47.809,35.503 47.809,54.934 v1(47.371,55.372) 47.968,55.969 51.626,55.969 52.476,56.82 58.693,56.82 60.96,54.552 v1(60.96,53.848)
NetLED1_1: LED1.1 R7.2 | length 2.2
  Top Layer w0.2: R7.2@16.35,5.5 LED1.1@18.55,5.5
NetLED1_2: LED1.2 U3.4 | length 7.5
  Top Layer w0.2: LED1.2@20.45,5.5 20.45,4.137 21.006,3.581 25.267,3.581 U3.4@25.267,2.496
NetLED2_1: LED2.1 R8.2 | length 2.2
  Top Layer w0.2: R8.2@46.35,5.5 LED2.1@48.55,5.5
RAM0_DATA0: HDR2.42 U1.56 | length 22.4
  Top Layer w0.2: U1.56@39.1,29.74 40.916,29.74 v1(41.021,29.845)
  Bottom Layer w0.2: HDR2.42@30.9,16.5 30.9,17.653 33.664,20.417 34.514,20.417 37.586,23.489 37.586,24.504 39.447,26.365 41.681,26.365 42.399,27.083 42.399,28.467 v1(41.021,29.845)
RAM0_DATA1: HDR2.40 U1.55 | length 21.7
  Top Layer w0.2: U1.55@39.1,28.47 40.84,28.47 v1(41.021,28.677)
  Bottom Layer w0.2: HDR2.40@30.1,16.5 30.1,17.78 33.137,20.817 34.279,20.817 37.186,23.724 37.186,24.669 39.282,26.765 41.51,26.765 41.91,27.165 41.91,28.27 41.529,28.651 v1(41.021,28.677)
RAM0_DATA2: HDR2.38 U1.54 | length 19.6
  Top Layer w0.2: U1.54@39.1,27.2 40.687,27.2 v1(41.021,27.534)
  Bottom Layer w0.2: HDR2.38@29.3,16.5 29.3,17.704 32.814,21.217 34.044,21.217 36.786,23.959 36.786,24.835 39.116,27.165 40.652,27.165 v1(41.021,27.534)
RAM0_DATA3: HDR2.36 U1.52 | length 12.8
  Top Layer w0.2: v1(35.23,23.495) 36.13,24.395 U1.52@36.13,25.5
  Bottom Layer w0.2: HDR2.36@28.5,16.5 28.5,17.78 32.337,21.617 33.352,21.617 v1(35.23,23.495)
RAM0_DATA4: HDR2.34 U1.51 | length 12.4
  Top Layer w0.2: v1(34.087,23.495) 34.86,24.268 U1.51@34.86,25.5
  Bottom Layer w0.2: HDR2.34@27.7,16.5 27.7,17.78 31.937,22.017 32.609,22.017 v1(34.087,23.495)
RAM0_DATA5: HDR2.32 U1.50 | length 12
  Top Layer w0.2: v1(32.944,23.495) 33.59,24.141 U1.50@33.59,25.5
  Bottom Layer w0.2: HDR2.32@26.9,16.5 26.9,17.78 31.537,22.417 31.866,22.417 v1(32.944,23.495)
RAM0_DATA6: HDR2.30 U1.49 | length 11.6
  Top Layer w0.2: v1(31.75,23.495) 32.32,24.065 U1.49@32.32,25.5
  Bottom Layer w0.2: HDR2.30@26.1,16.5 26.1,17.78 31.75,23.43 v1(31.75,23.495)
RAM0_DATA7: HDR2.28 U1.48 | length 11.4
  Top Layer w0.2: v1(30.48,23.495) 31.05,24.065 U1.48@31.05,25.5
  Bottom Layer w0.2: HDR2.28@25.3,16.5 25.3,17.653 30.48,22.833 v1(30.48,23.495)
RAM_ADDR0: HDR1.21 R5.2 U1.81 | length 24.8
  Top Layer w0.2: U1.81@29.78,54.3 29.78,55.561 v1(30.353,56.134) ; v1(37.084,58.801) 37.084,59.436 37.6,59.952 R5.2@37.6,60.95
  Bottom Layer w0.2: HDR1.21@22.9,60.5 22.9,58.761 23.241,58.42 23.241,57.785 23.724,57.302 29.185,57.302 31.598,54.889 34.569,54.889 35.992,56.312 35.992,57.709 v1(37.084,58.801)
RAM_ADDR1: HDR1.25 R4.2 U1.80 | length 21.2
  Top Layer w0.2: U1.80@31.05,54.3 31.05,55.688 v1(31.496,56.134) ; R4.2@35.1,60.95 35.1,60.023 35.56,59.563 v1(35.56,58.801)
  Bottom Layer w0.2: HDR1.25@24.5,60.5 24.5,59.066 25.857,57.709 29.921,57.709 32.309,55.321 34.366,55.321 35.56,56.515 v1(35.56,58.801)
REF_CLK: HDR2.4 U1.83 U2.43 | length 106.5
  Top Layer w0.2: U1.83@27.24,54.3 27.24,56.069 v1(27.305,56.134) 28.727,57.556 39.649,57.556 40.386,58.293 42.164,58.293 43.815,56.642 47.44,56.642 49.326,54.756 52.661,54.756 53.063,54.354 57.351,54.354 58.04,53.665 U2.43@58.04,51.35
  Bottom Layer w0.2: HDR2.4@15.7,16.5 15.7,17.7 7.975,25.425 7.975,33.993 3.556,38.412 3.556,54 6.693,57.137 9.487,57.137 10.49,58.141 18.764,58.141 20.77,56.134 v1(27.305,56.134)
